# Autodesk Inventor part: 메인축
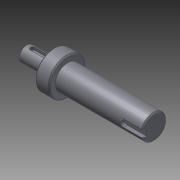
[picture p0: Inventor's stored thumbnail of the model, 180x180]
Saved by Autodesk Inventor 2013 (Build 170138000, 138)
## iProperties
Created: 2018-09
Part Number: 메인축
Document SubType Name: Modeling
Density: 1 g/cm^3
Material: 강철, 연강
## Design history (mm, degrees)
sketch "스케치1"
  geometry: L1 (34.997, -37.5)-(34.997, -77.5) reference; L2 (46.5, -38.401)-(46.5, -76.599) reference; L3 (12.497, -57.5)-(116.5, -57.5); L4 (12.497, -63.5)-(34.997, -63.5); L5 (34.997, -72.5)-(46.5, -72.5); L6 (46.5, -67.5)-(116.5, -67.5); L7 (116.5, -67.5)-(116.5, -57.5); L8 (12.497, -63.5)-(12.497, -57.5); 2 further points
  constraints: 12 end point, 5 point on line, 4 perpendicular, 1 midpoint, 1 parallel
  dimensions: "d0" = 20 diameter of L6 L3; "d1" = 30 diameter of L5 L3; "d2" = 22.5 distance of L4.start L4.end; "d3" = 70 distance of L6.start L6.end; "d5" = 12 diameter of L4 L3
revolve "회전1" sketch "스케치1" stored, may be unused: angle "d4" = 90 deg
chamfer "모따기1" distance "d6" = 1; stored, may be unused: second distance "d7" = 2, angle "d8" = 45 deg
node "작업 평면1"
sketch "스케치2"
  geometry: L1 (-11.25, -5)-(-11.25, 5) reference; L2 (-5.25, 2)-(4.75, 2); L3 (4.75, -2)-(-5.25, -2); A1 r 2 centre (4.75, 0) between (4.75, -2) and (4.75, 2); A2 r 2 centre (-5.25, 0) between (-5.25, 2) and (-5.25, -2); 2 further points
  constraints: 4 end point, 4 point on circle, 4 tangent, 2 centre point, 1 horizontal alignment, 1 midpoint, 1 parallel, 1 perpendicular
  dimensions: "d9" = 4 distance between parallel lines of L3 L2; "d10" = 14 dimension on A1 A2; "d11" = 4 distance edge to line of A2 L1
extrude "돌출1" cut sketch "스케치2" distance "d12" = 2.5; taper "d13" = 0 deg
node "작업 평면2"
sketch "스케치3"
  geometry: L1 (35, 9)-(35, -9) reference; L2 (35, 3)-(20, 3); L3 (20, -3)-(35, -3); A1 r 3 centre (20, 0) between (20, 3) and (20, -3); 2 further points
  constraints: 4 end point, 2 perpendicular, 2 point on circle, 2 point on line, 2 tangent, 1 centre point, 1 horizontal alignment, 1 midpoint
  dimensions: "d14" = 6 distance between parallel lines of L3 L2; "d15" = 18 dimension on A1 L1
extrude "돌출2" cut sketch "스케치3" distance "d16" = 3.5; taper "d17" = 0 deg
node "솔리드1"
node "참조1"
node "참조2"
